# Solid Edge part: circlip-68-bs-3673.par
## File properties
Title: External circlip for shaft Ø68 - BS 3673
Author: TraceParts S.A.
Template: Iso Metric Part.par
Last saved by: Nimesh.N
Revision: 5
Application: TraceParts
Company: TraceParts S.A.
Density: 7833.000 kg/m^3
Accuracy: 0.990
REFERENCE: BS 3673 - d 68 - d2 65
STANDARD: BS 3673
DESIGN: External circlip for shaft Ø68 - BS 3673
OMNICLASS23: 23.13.23.11.13.25
TraceParts.PartNumber: 10-08012002-076217
TraceParts.PartTitle: External circlip
TraceParts.InstanceId: 10-08012002-076217F0IQH3VN3VHCKCY888FUQY7VS
TraceParts.PartVersion: 1.3.0
TraceParts.PartLanguage: en
Username: Nimesh.N
Material: Steel
Face Style: Bronze (aged)
Fill Style: ANSI32(Steel)
Virtual Style: ANSI32(Steel)
Grouping: Metals\Steel
LibraryName: Materials
Coef. of Thermal Exp: 1.3e-05
Thermal Conductivity: 32.0
Specific Heat: 481.0
Modulus of Elasticity: 199947953000.0
Poisson's Ratio: 0.29
Yield Stress: 262000766.0
Ultimate Stress: 358527364.0
Elongation: 0.0
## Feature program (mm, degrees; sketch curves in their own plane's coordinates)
body "unnamed Body 1"
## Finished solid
Body 1: solid body, 16 faces, 40 edges, 28 vertices.
  Faces by surface: cylinder 8, plane 8
  Edges by curve: line 24, circle 16
Bounding box of the edges (mm): 73.667 x 79.510 x 2.500, from (-36.8333, -40.51, 0) to (36.8333, 39, 2.5).
Cylindrical faces by radius (mm): R1.5 x2, R4.1863 x4, R32.5 x1, R36.8333 x1
Planar faces by outward normal: +x 2, +z 1, -x 2, -y 2, -z 1
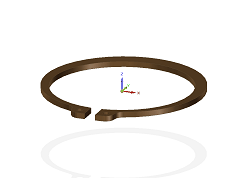
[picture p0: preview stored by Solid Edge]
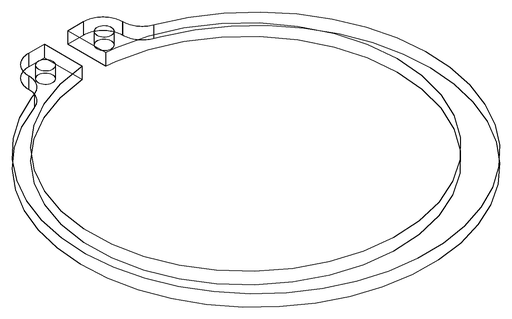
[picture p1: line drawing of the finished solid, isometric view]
